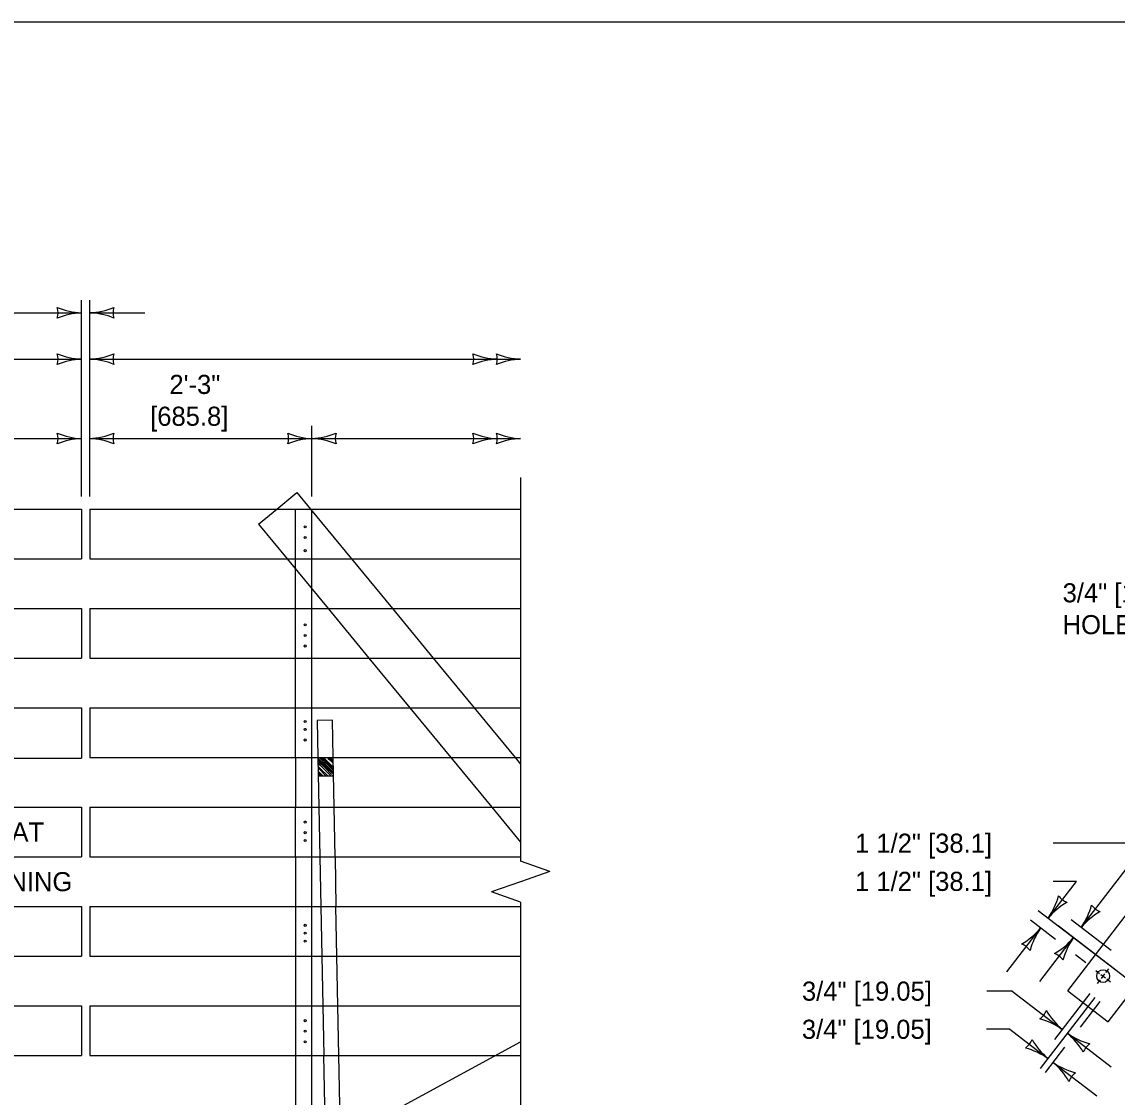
# Model space of a CAD drawing. Extents: x 49991 to 79985, y 47703 to 60542.
# Drawn here: x 50005.885 to 50009.323, y 49995.622 to 49998.999 of the extents above; entities that cross this region are included whole.
import ezdxf

# ---------------------------------------------------------------- set-up
doc = ezdxf.new("R2010")
doc.units = 0
for name, color, linetype in [('Level 1', 7, 'Continuous'), ('Level 2', 7, 'Continuous'), ('Level 3', 7, 'Continuous'), ('Level 4', 7, 'Continuous'), ('Level 5', 7, 'Continuous'), ('Level 6', 7, 'Continuous')]:
    doc.layers.add(name, color=color, linetype=linetype)

msp = doc.modelspace()

# ---------------------------------------------------------------- linework, layer by layer
at = {"layer": 'Level 1'}
for p, q in [((50009.1686, 49995.9554), (50010.6271, 49997.8561)), ((50009.2955, 49995.858), (50010.6794, 49997.6615)), ((50006.685, 49997.4683), (50006.7483, 49997.5204)), ((50006.7483, 49997.5204), (50006.7913, 49997.4683)), ((50001.6497, 49997.4683), (50006.0718, 49997.4683)), ((50006.0719, 49997.4683), (50006.0719, 49997.3123)), ((50006.0979, 49997.4683), (50006.0979, 49997.3123)), ((50006.0979, 49997.4683), (50007.4507, 49997.4683)), ((50001.9368, 49997.3123), (50006.0719, 49997.3123)), ((50006.0979, 49997.3123), (50007.4507, 49997.3123)), ((50006.7176, 49997.3123), (50006.8461, 49997.1563)), ((50006.9198, 49997.3123), (50007.0482, 49997.1563)), ((50006.7436, 49997.1563), (50006.7436, 49997.2807)), ((50006.7956, 49997.1563), (50006.7956, 49997.2176)), ((50002.2238, 49997.1563), (50006.0719, 49997.1563)), ((50006.0719, 49997.1563), (50006.0719, 49997.0008)), ((50006.0979, 49997.1563), (50006.0979, 49997.0003)), ((50006.0979, 49997.1563), (50007.4507, 49997.1563)), ((50002.5099, 49997.0008), (50006.0719, 49997.0008)), ((50006.0979, 49997.0003), (50007.4507, 49997.0003)), ((50006.7436, 49996.8443), (50006.7436, 49997.0003)), ((50006.7956, 49996.8443), (50006.7956, 49997.0003)), ((50006.9746, 49997.0003), (50007.1031, 49996.8443)), ((50007.1767, 49997.0003), (50007.3052, 49996.8443)), ((50002.7979, 49996.8443), (50006.0719, 49996.8443)), ((50006.0719, 49996.8443), (50006.0719, 49996.6868)), ((50006.0979, 49996.8443), (50006.0979, 49996.6883)), ((50006.0979, 49996.8443), (50007.4507, 49996.8443)), ((50003.0878, 49996.6868), (50006.0719, 49996.6868)), ((50006.0979, 49996.6883), (50007.4507, 49996.6883)), ((50006.7436, 49996.6883), (50006.7436, 49996.5323)), ((50006.7956, 49996.5323), (50006.7956, 49996.6883)), ((50006.814, 49996.6883), (50006.8171, 49996.5323)), ((50006.8654, 49996.5323), (50006.8623, 49996.6883)), ((50007.2316, 49996.6883), (50007.3601, 49996.5323)), ((50007.4337, 49996.6883), (50007.4507, 49996.6677)), ((50006.8152, 49996.6311), (50006.8635, 49996.6311)), ((50003.372, 49996.5323), (50006.0719, 49996.5323)), ((50006.0719, 49996.5323), (50006.0719, 49996.3763)), ((50006.0979, 49996.5323), (50006.0979, 49996.3763)), ((50006.0979, 49996.5323), (50007.4507, 49996.5323)), ((50003.6591, 49996.3763), (50006.0719, 49996.3763)), ((50006.0979, 49996.3763), (50007.4507, 49996.3763)), ((50006.7436, 49996.3763), (50006.7436, 49996.2203)), ((50006.7956, 49996.2203), (50006.7956, 49996.3763)), ((50006.8202, 49996.3763), (50006.8233, 49996.2203)), ((50006.8683, 49996.3763), (50006.8711, 49996.2203)), ((50003.9452, 49996.2208), (50006.0719, 49996.2208)), ((50006.0719, 49996.2208), (50006.0719, 49996.0643)), ((50006.0979, 49996.2203), (50006.0979, 49996.0643)), ((50006.0979, 49996.2203), (50007.4507, 49996.2203)), ((50004.2332, 49996.0643), (50006.0719, 49996.0643)), ((50006.0979, 49996.0643), (50007.4507, 49996.0643)), ((50006.7436, 49996.0643), (50006.7436, 49995.9083)), ((50006.7956, 49995.9083), (50006.7956, 49996.0643)), ((50006.8264, 49996.0643), (50006.8295, 49995.9083)), ((50006.8769, 49995.9083), (50006.874, 49996.0643)), ((50009.1686, 49995.9554), (50009.2955, 49995.858)), ((50004.5202, 49995.9083), (50006.0719, 49995.9083)), ((50006.0719, 49995.9083), (50006.0719, 49995.7523)), ((50006.0979, 49995.9083), (50006.0979, 49995.7523)), ((50006.0979, 49995.9083), (50007.4507, 49995.9083)), ((50006.3134, 49995.1775), (50007.4507, 49995.7955)), ((50004.8073, 49995.7523), (50006.0719, 49995.7523)), ((50006.0979, 49995.7523), (50007.3712, 49995.7523)), ((50006.7436, 49995.7523), (50006.7436, 49995.5963)), ((50006.7956, 49995.5963), (50006.7956, 49995.7523)), ((50006.8357, 49995.5963), (50006.8326, 49995.7523)), ((50006.8827, 49995.5963), (50006.8798, 49995.7523))]:
    msp.add_line(p, q, dxfattribs=at)
msp.add_lwpolyline([(49999.3835, 49998.9992), (50016.7501, 49998.9992), (50016.7501, 49987.7988), (49999.3835, 49987.7988)], close=True, dxfattribs=at)
for points in [[(50006.8633, 49996.6381), (50006.8441, 49996.6569), (50006.8301, 49996.6702), (50006.8185, 49996.6822), (50006.8141, 49996.6871)], [(50006.8631, 49996.6413), (50006.8541, 49996.6503), (50006.8416, 49996.6634), (50006.8253, 49996.681), (50006.818, 49996.6883)], [(50006.8631, 49996.6476), (50006.847, 49996.6643), (50006.8257, 49996.6859), (50006.8232, 49996.6883)], [(50006.8631, 49996.6512), (50006.8539, 49996.6615), (50006.8275, 49996.6883)], [(50006.863, 49996.6566), (50006.8549, 49996.6649), (50006.8409, 49996.6786), (50006.8316, 49996.6883)], [(50006.8627, 49996.67), (50006.861, 49996.6717), (50006.8501, 49996.6819), (50006.8443, 49996.6883)], [(50006.8626, 49996.6749), (50006.8611, 49996.6763), (50006.8488, 49996.6883)], [(50006.8625, 49996.6785), (50006.8561, 49996.6848), (50006.8533, 49996.6882), (50006.8533, 49996.6883)], [(50006.8623, 49996.6878), (50006.8618, 49996.6883)], [(50006.8142, 49996.6817), (50006.8144, 49996.6813), (50006.8286, 49996.6688), (50006.8426, 49996.6554), (50006.8601, 49996.6383)], [(50006.8143, 49996.6754), (50006.8165, 49996.6732), (50006.8209, 49996.6706), (50006.827, 49996.6661), (50006.8369, 49996.6559), (50006.857, 49996.6352)], [(50006.8539, 49996.632), (50006.8279, 49996.6577), (50006.8205, 49996.6644), (50006.8144, 49996.6693)], [(50006.8457, 49996.6311), (50006.823, 49996.6528), (50006.8146, 49996.6614)], [(50006.8396, 49996.6311), (50006.8147, 49996.6555), (50006.8147, 49996.6556)], [(50006.8303, 49996.6311), (50006.8162, 49996.6449), (50006.8149, 49996.6466)], [(50006.8268, 49996.6311), (50006.8212, 49996.6364), (50006.8149, 49996.6426)], [(50006.8219, 49996.6311), (50006.8211, 49996.6318), (50006.815, 49996.6375)], [(50006.8588, 49996.6333), (50006.8613, 49996.6311)], [(50006.8619, 49996.6364), (50006.8634, 49996.6351)]]:
    msp.add_lwpolyline(points, dxfattribs=at)
for centre, radius in [((50006.7745, 49997.413), 0.00327), ((50006.7745, 49997.3797), 0.00327), ((50006.7745, 49997.3381), 0.00327), ((50006.7745, 49997.1052), 0.00327), ((50006.7745, 49997.0719), 0.00327), ((50006.7745, 49997.0387), 0.00327), ((50006.7745, 49996.8016), 0.00327), ((50006.7745, 49996.7767), 0.00327), ((50006.7745, 49996.7434), 0.00327), ((50006.7745, 49996.4856), 0.00327), ((50006.7745, 49996.4523), 0.00327), ((50006.7745, 49996.4274), 0.00327), ((50006.7745, 49996.1612), 0.00327), ((50006.7745, 49996.1363), 0.00327), ((50006.7745, 49996.1113), 0.00327), ((50009.2796, 49996.0016), 0.02), ((50006.7745, 49995.8618), 0.00327), ((50006.7745, 49995.8285), 0.00327), ((50006.7745, 49995.7952), 0.00327)]:
    msp.add_circle(centre, radius, dxfattribs=at)
at = {"layer": 'Level 3'}
for p, q in [((50006.0719, 49997.5083), (50006.0719, 49998.1254)), ((50006.0979, 49997.5083), (50006.0979, 49998.1254)), ((50005.852, 49998.0854), (50006.0719, 49998.0854)), ((50006.0979, 49998.0854), (50006.2713, 49998.0854)), ((50001.0799, 49997.9399), (50006.0719, 49997.9399)), ((50006.0979, 49997.9399), (50007.4507, 49997.9399)), ((50006.7956, 49997.5083), (50006.7956, 49997.7304)), ((50005.3179, 49997.6904), (50006.0719, 49997.6904)), ((50006.0979, 49997.6904), (50006.7956, 49997.6904)), ((50006.7956, 49997.6904), (50007.4507, 49997.6904)), ((50009.4139, 49996.4192), (50009.1228, 49996.4192)), ((50009.2106, 49996.1543), (50009.4139, 49996.4192)), ((50009.1067, 49996.1836), (50009.1955, 49996.2993)), ((50009.1955, 49996.2993), (50009.1228, 49996.2993)), ((50009.0751, 49996.2081), (50009.6651, 49995.7554)), ((50009.1295, 49996.1168), (50009.0511, 49996.1769)), ((50009.3045, 49996.082), (50009.1788, 49996.1786)), ((50008.9774, 49996.0149), (50009.0829, 49996.1525)), ((50009.3195, 49996.0206), (50009.1386, 49996.1594)), ((50009.0808, 49995.9851), (50009.1864, 49996.1227)), ((50009.2247, 49996.0437), (50009.193, 49996.0681)), ((50008.9946, 49995.9545), (50008.9141, 49995.9545)), ((50008.9942, 49995.9548), (50009.1513, 49995.8343)), ((50009.2533, 49995.9344), (50009.082, 49995.7112)), ((50009.2375, 49995.9466), (50009.1269, 49995.8026)), ((50009.2692, 49995.9223), (50009.2074, 49995.8417)), ((50008.9865, 49995.8347), (50008.9138, 49995.8347)), ((50008.9864, 49995.8348), (50009.1063, 49995.7429)), ((50009.1672, 49995.8222), (50009.3048, 49995.7166)), ((50009.1587, 49995.7782), (50009.0979, 49995.699)), ((50009.1223, 49995.7307), (50009.2598, 49995.6252))]:
    msp.add_line(p, q, dxfattribs=at)
for centre, radius, start, end in [((50006.0811, 49998.3075), 0.2223, 247.456, 267.6395), ((50005.9437, 49998.0854), 0.0548, 342.1388, 17.8612), ((50006.0864, 49998.3181), 0.233, 272.8273, 292.0772), ((50006.2261, 49998.0854), 0.0548, 162.1388, 197.8612), ((50006.0834, 49997.8527), 0.233, 92.8273, 112.0772), ((50006.0887, 49997.8633), 0.2223, 67.456, 87.6395), ((50006.0811, 49998.162), 0.2223, 247.456, 267.6395), ((50005.9437, 49997.9399), 0.0548, 342.1388, 17.8612), ((50006.0834, 49997.7072), 0.233, 92.8273, 112.0772), ((50006.0864, 49998.1726), 0.233, 272.8273, 292.0772), ((50006.0887, 49997.7178), 0.2223, 67.456, 87.6395), ((50006.2261, 49997.9399), 0.0548, 162.1388, 197.8612), ((50007.3864, 49998.162), 0.2223, 247.456, 267.6395), ((50007.249, 49997.9399), 0.0548, 342.1388, 17.8612), ((50007.3888, 49997.7072), 0.233, 92.8273, 112.0772), ((50007.4599, 49998.162), 0.2223, 247.456, 267.6395), ((50007.3225, 49997.9399), 0.0548, 342.1388, 17.8612), ((50007.4622, 49997.7072), 0.233, 92.8273, 112.0772), ((50006.0811, 49997.9125), 0.2223, 247.456, 267.6395), ((50005.9437, 49997.6904), 0.0548, 342.1388, 17.8612), ((50006.0834, 49997.4577), 0.233, 92.8273, 112.0772), ((50006.0864, 49997.9231), 0.233, 272.8273, 292.0772), ((50006.0887, 49997.4683), 0.2223, 67.456, 87.6395), ((50006.2261, 49997.6904), 0.0548, 162.1388, 197.8612), ((50006.8048, 49997.9125), 0.2223, 247.456, 267.6395), ((50006.6674, 49997.6904), 0.0548, 342.1388, 17.8612), ((50006.8071, 49997.4577), 0.233, 92.8273, 112.0772), ((50006.7841, 49997.9231), 0.233, 272.8273, 292.0772), ((50006.7864, 49997.4683), 0.2223, 67.456, 87.6395), ((50006.9238, 49997.6904), 0.0548, 162.1388, 197.8612), ((50007.3864, 49997.9125), 0.2223, 247.456, 267.6395), ((50007.249, 49997.6904), 0.0548, 342.1388, 17.8612), ((50007.3888, 49997.4577), 0.233, 92.8273, 112.0772), ((50007.4599, 49997.9125), 0.2223, 247.456, 267.6395), ((50007.3225, 49997.6904), 0.0548, 342.1388, 17.8612), ((50007.4622, 49997.4577), 0.233, 92.8273, 112.0772), ((50008.9151, 49996.3161), 0.233, 325.3376, 344.5875), ((50009.1848, 49996.2854), 0.0548, 214.6491, 250.3715), ((50009.2774, 49996.0412), 0.2223, 119.9663, 140.1499), ((50009.0189, 49996.2868), 0.233, 325.3407, 344.5906), ((50009.2886, 49996.256), 0.0548, 214.6522, 250.3746), ((50009.3813, 49996.0118), 0.2223, 119.9694, 140.1529), ((50008.9121, 49996.2949), 0.2223, 299.9859, 320.1694), ((50009.2746, 49996.0201), 0.233, 145.3572, 164.6071), ((50009.0049, 49996.0508), 0.0548, 34.6687, 70.3911), ((50009.0158, 49996.2652), 0.2223, 299.9434, 320.1269), ((50009.378, 49995.9901), 0.233, 145.3147, 164.5646), ((50009.1083, 49996.021), 0.0548, 34.6262, 70.3486), ((50009.0496, 49995.9123), 0.0548, 304.6492, 340.3716), ((50009.0188, 49995.6427), 0.233, 55.3377, 74.5876), ((50009.2937, 49996.005), 0.2223, 209.9664, 230.1499), ((50009.0046, 49995.8209), 0.0548, 304.6551, 340.3775), ((50009.2488, 49995.9136), 0.2223, 209.9723, 230.1558), ((50009.0247, 49995.6515), 0.2223, 29.9504, 50.1339), ((50009.2997, 49996.0138), 0.233, 235.3217, 254.5716), ((50008.9738, 49995.5512), 0.233, 55.3436, 74.5935), ((50009.2689, 49995.7441), 0.0548, 124.6332, 160.3556), ((50008.9797, 49995.5601), 0.2223, 29.946, 50.1295), ((50009.2548, 49995.9224), 0.233, 235.3173, 254.5671), ((50009.224, 49995.6527), 0.0548, 124.6288, 160.3511)]:
    msp.add_arc(centre, radius, start, end, dxfattribs=at)
at = {"layer": 'Level 4'}
for p, q in [((50006.6279, 49997.4213), (50006.685, 49997.4683)), ((50006.7436, 49997.2807), (50006.7436, 49997.4683)), ((50006.7913, 49997.4683), (50006.9198, 49997.3123)), ((50006.7956, 49997.2176), (50006.7956, 49997.4683)), ((50006.6279, 49997.4213), (50006.7176, 49997.3123)), ((50006.7436, 49997.0003), (50006.7436, 49997.1563)), ((50006.7956, 49997.0003), (50006.7956, 49997.1563)), ((50006.8461, 49997.1563), (50006.9746, 49997.0003)), ((50007.0482, 49997.1563), (50007.1767, 49997.0003)), ((50006.7436, 49996.6883), (50006.7436, 49996.8443)), ((50006.7956, 49996.6883), (50006.7956, 49996.8443)), ((50007.1031, 49996.8443), (50007.2316, 49996.6883)), ((50007.3052, 49996.8443), (50007.4337, 49996.6883)), ((50006.86, 49996.8057), (50006.8117, 49996.8047)), ((50006.8117, 49996.8047), (50006.814, 49996.6883)), ((50006.8623, 49996.6883), (50006.86, 49996.8057)), ((50006.7436, 49996.3763), (50006.7436, 49996.5323)), ((50006.7956, 49996.3763), (50006.7956, 49996.5323)), ((50006.8171, 49996.5323), (50006.8202, 49996.3763)), ((50006.8683, 49996.3763), (50006.8654, 49996.5323)), ((50007.3601, 49996.5323), (50007.4507, 49996.4223)), ((50006.7436, 49996.2203), (50006.7436, 49996.0643)), ((50006.7956, 49996.0643), (50006.7956, 49996.2203)), ((50006.8233, 49996.2203), (50006.8264, 49996.0643)), ((50006.874, 49996.0643), (50006.8711, 49996.2203)), ((50006.7436, 49995.9083), (50006.7436, 49995.7523)), ((50006.7956, 49995.7523), (50006.7956, 49995.9083)), ((50006.8295, 49995.9083), (50006.8326, 49995.7523)), ((50006.8798, 49995.7523), (50006.8769, 49995.9083)), ((50007.3712, 49995.7523), (50007.4507, 49995.7523))]:
    msp.add_line(p, q, dxfattribs=at)
at = {"layer": 'Level 5'}
for p, q in [((50009.2564, 49996.0194), (50009.2683, 49996.0102)), ((50009.2723, 49996.0072), (50009.287, 49995.9959)), ((50009.274, 49995.9942), (50009.2853, 49996.0089)), ((50009.2883, 49996.0129), (50009.2974, 49996.0248)), ((50009.2618, 49995.9784), (50009.271, 49995.9903)), ((50009.2909, 49995.9929), (50009.3028, 49995.9838))]:
    msp.add_line(p, q, dxfattribs=at)
at = {"layer": 'Level 6'}
for p, q in [((50007.4507, 49997.5683), (50007.4507, 49996.3631)), ((50007.5421, 49996.3307), (50007.4507, 49996.3631)), ((50007.5421, 49996.3307), (50007.4507, 49996.2983)), ((50007.4507, 49996.2983), (50007.3593, 49996.2659)), ((50007.4507, 49996.2335), (50007.3593, 49996.2659)), ((50007.4507, 49996.2335), (50007.4507, 49995.0283))]:
    msp.add_line(p, q, dxfattribs=at)

# ---------------------------------------------------------------- texts
at = {"layer": 'Level 2'}
for s, p in [('2\'-3"', (50006.3483, 49997.8304)), ('[685.8]', (50006.2878, 49997.7304)), ('3/4" [19.05] DIA.', (50009.1524, 49997.1758)), ('HOLES (TYP.)', (50009.1524, 49997.0758)), ('SLAT', (50005.7542, 49996.4243)), ('1 1/2" [38.1]', (50008.5007, 49996.3892)), ('FASTENING', (50005.5842, 49996.2683)), ('1 1/2" [38.1]', (50008.5007, 49996.2693)), ('3/4" [19.05]', (50008.3341, 49995.9245)), ('3/4" [19.05]', (50008.3338, 49995.8047))]:
    msp.add_text(s, height=0.06, dxfattribs=at).set_placement(p)

doc.saveas('drawing.dxf')
